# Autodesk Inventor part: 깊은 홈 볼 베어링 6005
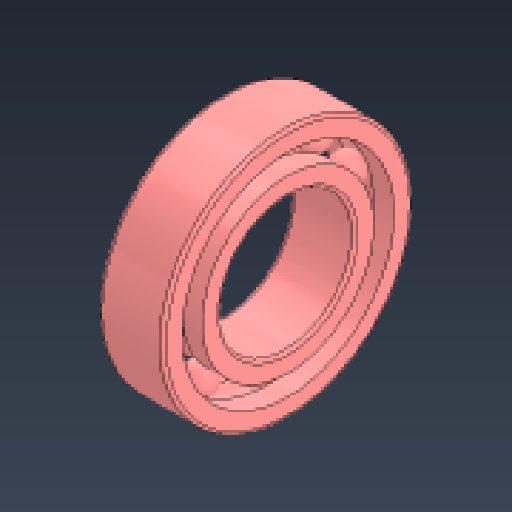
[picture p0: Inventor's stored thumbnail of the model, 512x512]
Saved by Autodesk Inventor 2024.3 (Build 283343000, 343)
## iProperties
Created: 2025-07
Part Number: 깊은 홈 볼 베어링 6005
Material: 강철, 연강
Description: 깊은 그루브 볼 베어링
Document SubType Name: Modeling
Designer: user
Density: 7.85 g/cm^3
Appearance: 기본값
Sending System: Autodesk Inventor 2026
Preprocessor: ST-DEVELOPER v20.1
Author: jhkim
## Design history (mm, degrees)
feature "Solid1"
feature "Solid1:1"
feature "Solid1:2"
feature "Solid1:3"
feature "Solid1:4"
feature "Solid1:5"
feature "Solid1:6"
feature "Solid1:7"
feature "Solid1:8"
feature "Solid1:9"
feature "Solid1:10"
feature "Solid1:11"
node "솔리드1"
node "솔리드2"
node "솔리드3"
node "솔리드4"
node "솔리드5"
node "솔리드6"
node "솔리드7"
node "솔리드8"
node "솔리드9"
node "솔리드10"
node "솔리드11"
node "솔리드12"
